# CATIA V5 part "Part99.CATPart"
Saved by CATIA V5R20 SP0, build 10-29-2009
Part number: FA 063200-1
Revision: ANY
Definition: UNKNOWN
Nomenclature: FA 063200-1
Source: Unknown
Bounding box of the stored display mesh (mm): x -2.5 to 2.5, y 0.15 to 2.5, z -2.5 to 2.5
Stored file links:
  C:\Users\Utente\Desktop\IO LAVORO\3D X SITO CF\CUMSA\3D files FA\FA 063205-20\Part99.CATPart

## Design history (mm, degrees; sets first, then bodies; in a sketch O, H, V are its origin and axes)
Body1 "Cortar-Extruir1" (main body)
  Solid1: solid without history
